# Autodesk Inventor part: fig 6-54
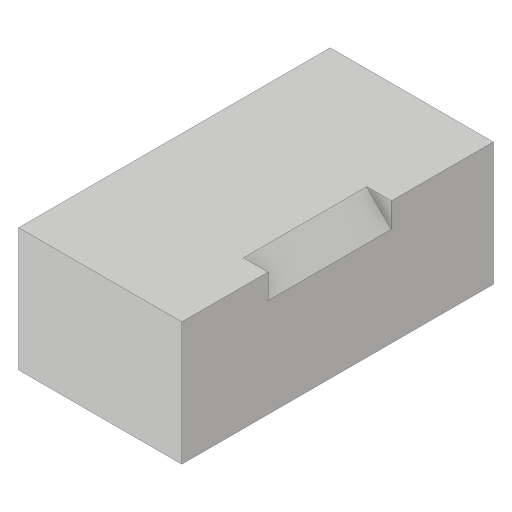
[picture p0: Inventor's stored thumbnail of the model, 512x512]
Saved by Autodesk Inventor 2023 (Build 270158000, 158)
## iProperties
Created: 2018-03
Part Number: fig 6-54
Material: Generic
Document SubType Name: Modeling
Designer: CADCIM 00
Density: 1 g/cm^3
Appearance: Default
Author: CADCIM 00
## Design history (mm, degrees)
sketch "Sketch1"
  geometry: L1 (0, 0)-(13.237, 0); L2 (13.237, 0)-(13.237, -25.282); L3 (13.237, -25.282)-(0, -25.282); L4 (0, -25.282)-(0, 0)
  constraints: 8 end point, 2 parallel, 1 horizontal, 1 perpendicular
extrude "Extrusion1" new body sketch "Sketch1" distance "d0" = 10; taper "d1" = 0 deg
chamfer "Chamfer1" distance "d2" = 2; stored, may be unused: second distance "d3" = 2, angle "d4" = 45 deg; dims "d5" = 7, "d6" = 10, "d7" = 8.28246
body "Solid1"
